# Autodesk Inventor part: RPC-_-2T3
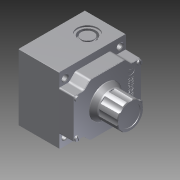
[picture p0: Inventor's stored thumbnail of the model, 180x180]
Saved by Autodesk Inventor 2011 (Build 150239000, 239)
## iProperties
Created: 2012-01
Part Number: RPC-_-2T3
Document SubType Name: Modeling
Designer: khramov
Density: 1 g/cm^3
Author: khramov
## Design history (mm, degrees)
derived "RPC_2T3_31.iam"
node "Твердое тело1"
node "0113138.ipt:1"
node "0113007.ipt:1"
node "0110595.ipt:1"
sketch "0550325.ipt:1"
sketch "0113050.ipt:1"
sketch "0113050.ipt:2"
